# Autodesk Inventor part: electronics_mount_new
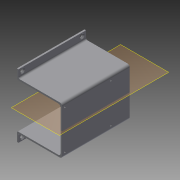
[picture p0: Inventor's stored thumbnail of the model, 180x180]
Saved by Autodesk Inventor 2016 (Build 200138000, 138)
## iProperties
Created: 2014-08
Part Number: electronics_mount_new
Material: Generic
Document SubType Name: Modeling
Designer: James
Density: 1 g/cm^3
Appearance: Default
Author: James
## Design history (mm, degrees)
sketch "Sketch1"
  geometry: L1 (-31.969, 39.443)-(53.031, 39.443); L2 (53.031, 39.443)-(53.031, -16.557); L3 (53.031, -16.557)-(-31.969, -16.557); L4 (-31.969, -16.557)-(-31.969, 39.443); 1 further point
  constraints: 8 end point, 2 parallel, 1 horizontal, 1 perpendicular
  dimensions: "d0" = 85 distance between parallel lines of L2 L4; "d1" = 56 distance between parallel lines of L3 L1
extrude "Extrusion1" new body sketch "Sketch1" distance "d2" = 2; taper "d3" = 0 deg
sketch "Sketch2"
  geometry: L1 (-39.443, 53.031)-(-39.443, -31.969) reference; L2 (-39.443, -31.969)-(16.557, -31.969) reference; 5 further points
  dimensions: "d4" = 3.5 distance from line of L1 point (-35.943, -28.469); "d5" = 3.5 distance from line of L2 point (-35.943, -28.469); "d6" = 3.5 distance from line of L1 point (-35.943, 29.531) (= d4); "d7" = 58 distance of point (-35.943, -28.469) point (-35.943, 29.531); "d8" = 3.5 distance from line of L2 point (13.057, -28.469) (= d5); "d9" = 58 distance of point (13.057, -28.469) point (13.057, 29.531) (= d7); "d36" = 49 distance of point (13.057, -28.469) point (-35.943, -28.469); "d37" = 49 distance of point (-35.943, 29.531) point (13.057, 29.531)
hole "Hole1" sketch "Sketch2" at (-35.943, 29.531), (13.057, 29.531), (13.057, -28.469), (-35.943, -28.469) diameter "d11" = 2.013; stored, may be unused: countersink angle "d15" = 90 deg, drill point angle "d17" = 118 deg; dims "d12" = 6, "d13" = 4, "d14" = 2, "d16" = 8
sketch "Sketch10"
  geometry: 2 further points
hole "Hole4" sketch "Sketch10" at (7.309, 54.858) diameter "d57" = 2.013; stored, may be unused: countersink angle "d61" = 90 deg, drill point angle "d63" = 118 deg; dims "d58" = 5, "d59" = 4, "d60" = 2, "d62" = 7.6
pattern_linear "Rectangular Pattern1" dims "d66" = 30
sketch "Sketch11"
  geometry: L1 (-2, 85)-(-2, 0) reference; L2 (-2, 0)-(53, 0); L3 (53, 0)-(53, 85); L4 (53, 85)-(-2, 85); L5 (-2, 85)-(-2, 0); L6 (0, 85)-(-2, 85) reference; 1 further point
  constraints: 8 end point, 2 parallel, 1 horizontal, 1 perpendicular
  dimensions: "d70" = 55 distance between parallel lines of L1 L3; "d78" = 85 distance between parallel lines of L4 L2 (= d79); "d79" = 85 distance between parallel lines of L6 L2 (derived)
extrude "Extrusion6" join sketch "Sketch11" distance "d71" = 2; taper "d72" = 0 deg
fillet "Fillet3" dims "d73" = 3
workplane "Work Plane1"
sketch "Sketch12"
  geometry: L1 (0, 85)-(0, 0) reference; L2 (0, 0)-(-12, 0); L3 (-12, 0)-(-12, 85); L4 (-12, 85)-(0, 85); L5 (0, 85)-(0, 0); L6 (56, 0)-(1, 0) reference; L7 (56, 85)-(1, 85) reference; 1 further point
  constraints: 8 end point, 2 parallel, 1 horizontal, 1 perpendicular
  dimensions: "d74" = 12 distance between parallel lines of L1 L3; "d80" = 85 distance between parallel lines of L6 L7 (derived); "d81" = 85 distance between parallel lines of L2 L4 (= d80)
extrude "Extrusion7" join sketch "Sketch12" distance "d75" = 2; taper "d76" = 0 deg
fillet "Fillet4" dims "d77" = 2
sketch "Sketch13"
  geometry: L1 (12, 85)-(4, 85) reference; L2 (4, 0)-(12, 0) reference; L3 (12, 0)-(12, 85) reference; 3 further points
  dimensions: "d82" = 5 distance from line of L1 point (8, 80); "d83" = 5 distance from line of L2 point (8, 5) (= d82); "d84" = 4 distance from line of point (8, 5) L3 (= d85); "d85" = 4 distance from line of L3 point (8, 80)
hole "Hole5" sketch "Sketch13" at (8, 5), (8, 80) diameter "d86" = 3.4; stored, may be unused: countersink angle "d90" = 90 deg, drill point angle "d92" = 118 deg; dims "d87" = 8, "d88" = 6.3, "d89" = 2, "d91" = 11.8
mirror "Mirror3"
body "Solid1"
